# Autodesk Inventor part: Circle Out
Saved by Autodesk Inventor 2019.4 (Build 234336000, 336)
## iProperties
Created: 2020-12
Part Number: Circle Out
Material: Generic
Document SubType Name: Modeling
Designer: Administrator
Density: 1 g/cm^3
Appearance: Default
Title: Circle Out
Author: Administrator
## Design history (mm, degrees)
feature "Body1"
body "Solid1"
